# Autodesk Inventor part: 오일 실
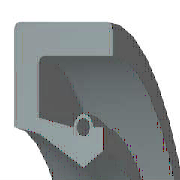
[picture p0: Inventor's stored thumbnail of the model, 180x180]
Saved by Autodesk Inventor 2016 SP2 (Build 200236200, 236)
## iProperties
IsCustomPart: 1
Created: 2015-10
Part Number: 오일 실
Material: 고무
Description: 오일-실
Document SubType Name: Modeling
Standard: KS B 2804
Designer: mdu
Standards Organization: KS
Language: ko-KR
Size Designation: S - 25 38 8
Categories: <MemberInstance><Categories><Category DisplayName="샤프트 부품" InternalName="7f7aeb1f-a693-4053-b835-cee3144e0d98" Mnemonic="SHFT"><Category DisplayName="실링" Intern
Density: 0.93 g/cm^3
Appearance: 고무 - 검은색 - 버전 1.1
Mass: 2.23721 g
Surface Area: 37.0166 cm^2
Volume: 2.4056 cm^3
Author: mdu
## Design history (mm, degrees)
revolve "본체" stored, may be unused: angle "d17" = 90 deg
revolve "스프링1" stored, may be unused: angle "d18" = 90 deg
body "Solid1"
sketch "스케치1"
  geometry: L1 (0, 19)-(8, 19); L2 (8, 19)-(8, 17.75); L3 (8, 17.75)-(1.75, 17.75); L4 (0, 19)-(0, 14.6); L5 (0, 14.6)-(1.75, 14.25); L6 (1.75, 14.25)-(4.9, 12.5); L7 (4.9, 12.5)-(0, 12.5); L8 (6.3, 13.375)-(6.3, 14.6); L9 (0, 0)-(9.586, 0) reference; L10 (4.9, 12.5)-(6.3, 13.375); L11 (0, 18)-(0, -3) reference; L12 (-1.917, 0)-(11.503, 0) reference; L13 (4.2, 14.6)-(1.75, 15.09); L14 (1.75, 15.09)-(1.75, 17.75); L15 (6.3, 14.6)-(5.6, 14.6); C1 r 0.455 at (4.9, 14.6); A1 r 0.7 centre (4.9, 14.6) between (5.6, 14.6) and (4.2, 14.6)
  constraints: 26 end point, 5 horizontal alignment, 4 perpendicular, 2 centre point, 2 collinear, 2 horizontal, 2 parallel, 2 point on circle, 2 point on line, 2 vertical alignment, 1 coincident
  dimensions: "d0" = 38 diameter of L1 L9 (= SD2); "d1" = 26.75 diameter of L8.start L9 (= ABDM); "d2" = 1.25 distance of L1.end L2.end (computed from SD); "d3" = 0.91 diameter of C1 (= SPDI); "d4" = 1.4 diameter of A1 (= SPDA); "d5" = 25 diameter of L6.end L9 (= NND); "d6" = 28.5 diameter of L5.end L9 (= TKDM); "d7" = 29.2 diameter of L4.end L9 (= HLDM); "d8" = 4.9 distance from line of C1.centre L4 (= SPDST); "d9" = 6.3 distance between parallel lines of L8 L4 (= SDI); "d10" = 8 distance between parallel lines of L2 L4 (= SWDT); "d12" = 1.75 distance between parallel lines of L14 L4 (= SD)
fillet "모깎기1" dims "d11" = 0.3 (= RR)
other parameters: "SD2" = 38 [user parameter; used in 1 equation term], "SWDT" = 8 [user parameter; used in 1 equation term], "RR" = 0.3 [user parameter; used in 1 equation term], "SD" = 1.75 [user parameter; used in 2 equation terms], "NND" = 25 [user parameter; used in 1 equation term], "SPDA" = 1.4 [user parameter; used in 1 equation term], "SPDI" = 0.91 [user parameter; used in 1 equation term], "TKDM" = 28.5 [user parameter; used in 1 equation term], "HLDM" = 29.2 [user parameter; used in 1 equation term], "ABDM" = 26.75 [user parameter; used in 1 equation term], "SDI" = 6.3 [user parameter; used in 1 equation term], "SPDST" = 4.9 [user parameter; used in 1 equation term], "d13" = 0, "d14" = 0, "d15" = 0, "LAB" = 0.35 [user parameter]
